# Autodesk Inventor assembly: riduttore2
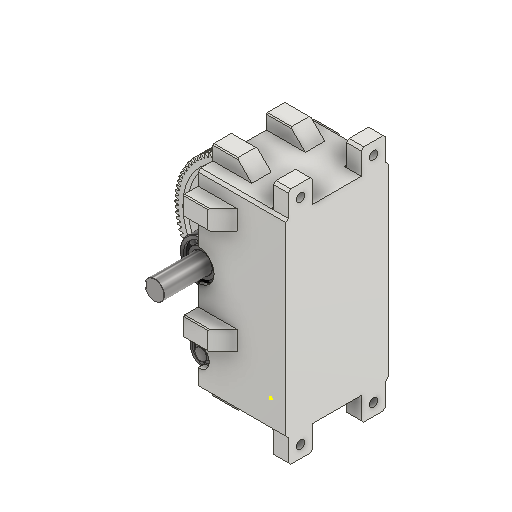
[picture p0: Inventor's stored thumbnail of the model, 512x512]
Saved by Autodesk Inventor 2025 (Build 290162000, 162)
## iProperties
Created: 2026-05
Part Number: riduttore2
Document SubType Name: Assembly
Designer: R5800u
Author: R5800u
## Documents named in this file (15)
- C:\Users\Ryzen5700u\Desktop\riduttore pompa\riduttore2.iam
- C:\Users\Ryzen5700u\Desktop\riduttore pompa\Ingranaggi cilindrici1.iam
- C:\Users\Ryzen5700u\Desktop\riduttore pompa\Albero1.ipt
- C:\Users\Ryzen5700u\Desktop\riduttore pompa\Albero2.ipt
- C:\Users\Ryzen5700u\Desktop\riduttore pompa\Connessione a chiavetta4.iam
- C:\Users\Ryzen5700u\Desktop\riduttore pompa\Connessione a chiavetta5.iam
- C:\Users\Ryzen5700u\Desktop\riduttore pompa\distanziale_condeotta.ipt
- C:\Users\Ryzen5700u\Desktop\riduttore pompa\distanziale_pignone.ipt
- C:\Users\Ryzen5700u\Desktop\riduttore pompa\BS 290 SKF - SKF 6308-Z.ipt
- C:\Users\Ryzen5700u\Desktop\riduttore pompa\BS 290 SKF - SKF 6305-Z.ipt
- C:\Users\Ryzen5700u\Desktop\riduttore pompa\carter.ipt
- C:\Users\Ryzen5700u\Desktop\riduttore pompa\riduttore2\Design Accelerator\Connessione a chiavetta1.iam
- C:\Users\Ryzen5700u\Desktop\riduttore pompa\riduttore2\Design Accelerator\Connessione a chiavetta2.iam
- C:\Users\Ryzen5700u\Desktop\riduttore pompa\riduttore2\Design Accelerator\Connessione a chiavetta3.iam
- C:\Users\Ryzen5700u\Desktop\riduttore pompa\carter_MIR.ipt
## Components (16 placed, 9 different names)
1. Ingranaggi cilindrici:1 [sub-assembly] — Coincidente:1, Coincidente:2, Coincidente:3, Coincidente:4, Coincidente:19, Coincidente:20, Allineato:3
2. Albero:1
3. Albero:1 — Coincidente:3, Coincidente:4, Coincidente:12, Coincidente:14, Coincidente:18
4. BS 290 SKF- con schermatura Z SKF 6308-Z:1 — Coincidente:6
5. BS 290 SKF- con schermatura Z SKF 6305-Z:2 — Coincidente:12
6. Connessione a chiavetta:2 [sub-assembly] — Allineato:1, Angolo:1, Coincidente:13
7. Connessione a chiavetta:4 [sub-assembly]
8. BS 290 SKF- con schermatura Z SKF 6305-Z:1 — Coincidente:14, Allineato:2
9. distanziale_condeotta:1 — Coincidente:15, Coincidente:17, Coincidente:20
10. BS 290 SKF- con schermatura Z SKF 6308-Z:2 — Coincidente:16, Coincidente:17, Allineato:2
11. distanziale_pignone:1 — Coincidente:18, Coincidente:19
12. carter:1
13. Connessione a chiavetta:5 [sub-assembly]
14. Connessione a chiavetta:6 [sub-assembly]
15. Connessione a chiavetta:7 [sub-assembly]
16. carter_MIR:1 — Coincidente:21
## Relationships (19: Mate 15, Flush 3, Angle 1)
- Coincidente:1 [Mate]: Ingranaggi cilindrici:1
- Coincidente:2 [Mate]: Ingranaggi cilindrici:1
- Coincidente:3 [Mate]: Ingranaggi cilindrici:1 ↔ Albero:1
- Coincidente:4 [Mate]: Ingranaggi cilindrici:1 ↔ Albero:1
- Coincidente:6 [Mate]: BS 290 SKF- con schermatura Z SKF 6308-Z:1
- Coincidente:12 [Mate]: Albero:1 ↔ BS 290 SKF- con schermatura Z SKF 6305-Z:2
- Allineato:1 [Flush]: Connessione a chiavetta:2
- Angolo:1 [Angle]: Connessione a chiavetta:2
- Coincidente:13 [Mate]: Connessione a chiavetta:2
- Coincidente:14 [Mate]: Albero:1 ↔ BS 290 SKF- con schermatura Z SKF 6305-Z:1
- Coincidente:15 [Mate]: distanziale_condeotta:1
- Coincidente:16 [Mate]: BS 290 SKF- con schermatura Z SKF 6308-Z:2
- Coincidente:17 [Mate]: distanziale_condeotta:1 ↔ BS 290 SKF- con schermatura Z SKF 6308-Z:2
- Allineato:2 [Flush]: BS 290 SKF- con schermatura Z SKF 6305-Z:1 ↔ BS 290 SKF- con schermatura Z SKF 6308-Z:2
- Coincidente:18 [Mate]: Albero:1 ↔ distanziale_pignone:1
- Coincidente:19 [Mate]: Ingranaggi cilindrici:1 ↔ distanziale_pignone:1
- Coincidente:20 [Mate]: Ingranaggi cilindrici:1 ↔ distanziale_condeotta:1
- Allineato:3 [Flush]: Ingranaggi cilindrici:1
- Coincidente:21 [Mate]: carter_MIR:1
